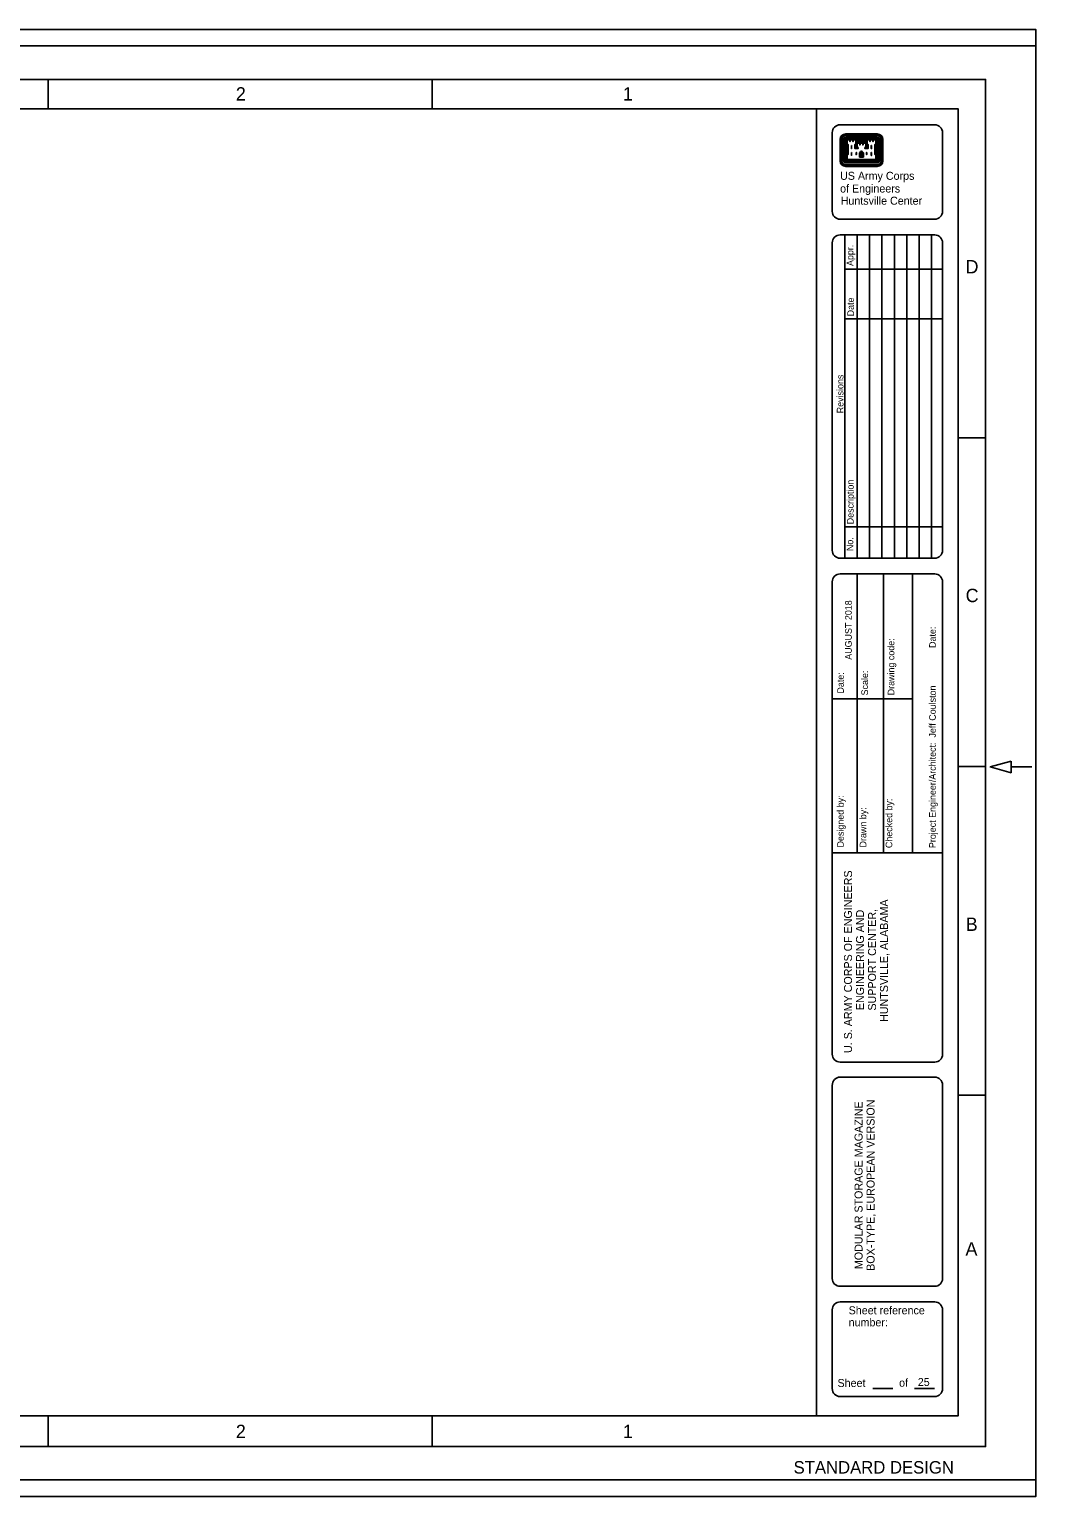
# Model space of a CAD drawing. Extents: x -0.04 to 2.79, y -0.02 to 1.81.
# Drawn here: x 1.534 to 2.792, y -0.021 to 1.813 of the extents above; entities that cross this region are included whole.
import ezdxf

# ---------------------------------------------------------------- set-up
doc = ezdxf.new("R2010")
doc.units = 0
for name, color, linetype in [('G-ANNO-NPLT', 7, 'Continuous'), ('G-ANNO-PLOT', 7, 'Continuous'), ('G-ANNO-TTLB', 7, 'Continuous')]:
    doc.layers.add(name, color=color, linetype=linetype)

msp = doc.modelspace()

# ---------------------------------------------------------------- linework, layer by layer
at = {"layer": 'G-ANNO-NPLT'}
msp.add_lwpolyline([(-0.0417, 1.8125), (2.7917, 1.8125), (2.7917, -0.0208), (-0.0417, -0.0208)], close=True, dxfattribs=at)
at = {"layer": 'G-ANNO-PLOT'}
for p, q in [((2.7917, 1.8125), (-0.0417, 1.8125)), ((2.7917, 1.8125), (2.7917, -0.0208)), ((2.7917, -0.0208), (-0.0417, -0.0208))]:
    msp.add_line(p, q, dxfattribs=at)
msp.add_lwpolyline([(0, 0), (2.7917, 0), (2.7917, 1.7917), (0, 1.7917)], close=True, dxfattribs=at)
at = {"layer": 'G-ANNO-TTLB'}
for p, q in [((1.5578, 1.7131), (1.5578, 1.75)), ((2.0378, 1.7131), (2.0378, 1.75)), ((2.5178, 0.0803), (2.5178, 1.7131)), ((2.5473, 1.6749), (2.5473, 1.6483)), ((2.5477, 1.6749), (2.5477, 1.6483)), ((2.5484, 1.6749), (2.5484, 1.6483)), ((2.5489, 1.6749), (2.5489, 1.6483)), ((2.5494, 1.6749), (2.5494, 1.6483)), ((2.5517, 1.6749), (2.5517, 1.6483)), ((2.5523, 1.6749), (2.5523, 1.6483)), ((2.5528, 1.6749), (2.5528, 1.6483)), ((2.5534, 1.6749), (2.5534, 1.6483)), ((2.554, 1.6749), (2.554, 1.6483)), ((2.5938, 1.6819), (2.5543, 1.6819)), ((2.5938, 1.6815), (2.5543, 1.6815)), ((2.5938, 1.6809), (2.5543, 1.6809)), ((2.5938, 1.6804), (2.5543, 1.6804)), ((2.5938, 1.6798), (2.5543, 1.6798)), ((2.5938, 1.6776), (2.5543, 1.6776)), ((2.5938, 1.677), (2.5543, 1.677)), ((2.5938, 1.6764), (2.5543, 1.6764)), ((2.5938, 1.6758), (2.5543, 1.6758)), ((2.5938, 1.6753), (2.5543, 1.6753)), ((2.5545, 1.6749), (2.5545, 1.6484)), ((2.5551, 1.6749), (2.5551, 1.649)), ((2.5555, 1.6692), (2.5555, 1.6556)), ((2.5561, 1.6686), (2.5561, 1.6563)), ((2.5679, 1.6747), (2.5801, 1.6747)), ((2.5679, 1.6742), (2.5801, 1.6742)), ((2.5679, 1.6737), (2.5801, 1.6737)), ((2.5679, 1.6731), (2.5801, 1.6731)), ((2.5679, 1.6725), (2.5801, 1.6725)), ((2.5679, 1.672), (2.5801, 1.672)), ((2.5679, 1.6714), (2.5801, 1.6714)), ((2.592, 1.6686), (2.592, 1.6563)), ((2.5925, 1.6692), (2.5925, 1.6557)), ((2.593, 1.6749), (2.593, 1.649)), ((2.5935, 1.6749), (2.5935, 1.6484)), ((2.5941, 1.6749), (2.5941, 1.6483)), ((2.5947, 1.6749), (2.5947, 1.6483)), ((2.5953, 1.6749), (2.5953, 1.6483)), ((2.5958, 1.6749), (2.5958, 1.6483)), ((2.5964, 1.6749), (2.5964, 1.6483)), ((2.5986, 1.6749), (2.5986, 1.6483)), ((2.5992, 1.6749), (2.5992, 1.6483)), ((2.5997, 1.6749), (2.5997, 1.6483)), ((2.6003, 1.6749), (2.6003, 1.6483)), ((2.6007, 1.6749), (2.6007, 1.6483)), ((2.5714, 1.6528), (2.5714, 1.6572)), ((2.5714, 1.6528), (2.5767, 1.6528)), ((2.5719, 1.6528), (2.5719, 1.6572)), ((2.5725, 1.6528), (2.5725, 1.6572)), ((2.5731, 1.6528), (2.5731, 1.6572)), ((2.5737, 1.6528), (2.5737, 1.6572)), ((2.5744, 1.6528), (2.5744, 1.6572)), ((2.575, 1.6528), (2.575, 1.6572)), ((2.5755, 1.6528), (2.5755, 1.6572)), ((2.5761, 1.6528), (2.5761, 1.6572)), ((2.5767, 1.6528), (2.5767, 1.6572)), ((2.5938, 1.6478), (2.5543, 1.6478)), ((2.5938, 1.6473), (2.5543, 1.6473)), ((2.5938, 1.6467), (2.5543, 1.6467)), ((2.5938, 1.6462), (2.5543, 1.6462)), ((2.5938, 1.6456), (2.5543, 1.6456)), ((2.5938, 1.6433), (2.5543, 1.6433)), ((2.5938, 1.6428), (2.5543, 1.6428)), ((2.5938, 1.6423), (2.5543, 1.6423)), ((2.5938, 1.6417), (2.5543, 1.6417)), ((2.5938, 1.6412), (2.5543, 1.6412)), ((2.5935, 1.6484), (2.5545, 1.6484)), ((2.593, 1.649), (2.5551, 1.649)), ((2.5532, 1.5557), (2.5532, 1.1517)), ((2.5686, 1.5557), (2.5686, 1.1517)), ((2.5842, 1.5557), (2.5842, 1.1517)), ((2.5996, 1.5557), (2.5996, 1.1517)), ((2.6151, 1.5557), (2.6151, 1.1517)), ((2.6306, 1.5557), (2.6306, 1.1517)), ((2.646, 1.5557), (2.646, 1.1517)), ((2.6615, 1.5557), (2.6615, 1.1517)), ((2.5532, 1.513), (2.6754, 1.513)), ((2.5532, 1.4507), (2.6754, 1.4507)), ((2.695, 1.3022), (2.7292, 1.3022)), ((2.5532, 1.1911), (2.6754, 1.1911)), ((2.5685, 1.1321), (2.5685, 0.976)), ((2.6014, 1.1321), (2.6014, 0.976)), ((2.6377, 1.1321), (2.6377, 0.7837)), ((2.6377, 0.976), (2.5376, 0.976)), ((2.5685, 0.976), (2.5685, 0.7837)), ((2.6014, 0.976), (2.6014, 0.7837)), ((2.695, 0.8914), (2.7292, 0.8914)), ((2.7609, 0.891), (2.787, 0.891)), ((2.6754, 0.7837), (2.5376, 0.7837)), ((2.5474, 0.5221), (2.6655, 0.5221)), ((2.695, 0.4806), (2.7292, 0.4806)), ((2.5883, 0.1141), (2.6134, 0.1141)), ((2.6403, 0.1141), (2.6654, 0.1141)), ((1.5578, 0.0418), (1.5578, 0.0803)), ((2.0378, 0.0418), (2.0378, 0.0803))]:
    msp.add_line(p, q, dxfattribs=at)
for points in [[(0.0833, 0.0417), (2.7292, 0.0417), (2.7292, 1.75), (0.2515, 1.75)], [(0.1166, 0.0803), (2.695, 0.0803), (2.695, 1.7131), (0.1166, 1.7131)], [(2.5474, 1.6934), (2.6655, 1.6934)], [(2.5376, 1.5851), (2.5376, 1.6835)], [(2.5555, 1.6749), (2.5555, 1.6698), (2.5567, 1.6686), (2.5567, 1.6563), (2.5555, 1.6551), (2.5555, 1.6494), (2.5926, 1.6494), (2.5926, 1.6551), (2.5914, 1.6563), (2.5914, 1.6686), (2.5926, 1.6698), (2.5926, 1.6749), (2.5877, 1.6749), (2.5839, 1.6749), (2.5804, 1.6749), (2.5804, 1.6698), (2.5817, 1.6686), (2.5817, 1.6642), (2.5789, 1.6642), (2.5789, 1.6646), (2.5801, 1.6657), (2.5801, 1.6708), (2.5752, 1.6708), (2.5714, 1.6708), (2.5679, 1.6708), (2.5679, 1.6657), (2.5691, 1.6646), (2.5691, 1.6642), (2.5664, 1.6642), (2.5664, 1.6686), (2.5676, 1.6698), (2.5676, 1.6749), (2.5626, 1.6749), (2.5589, 1.6749), (2.5555, 1.6749)], [(2.5561, 1.6743), (2.5561, 1.67), (2.5573, 1.6688), (2.5573, 1.656), (2.5561, 1.6549), (2.5561, 1.65), (2.592, 1.65), (2.592, 1.6549), (2.5909, 1.656), (2.5909, 1.6688), (2.592, 1.67), (2.592, 1.6743), (2.5886, 1.6743), (2.5886, 1.6723), (2.5883, 1.6723), (2.5883, 1.6743), (2.5848, 1.6743), (2.5848, 1.6723), (2.5845, 1.6723), (2.5845, 1.6743), (2.581, 1.6743), (2.581, 1.67), (2.5822, 1.6688), (2.5822, 1.6636), (2.5784, 1.6636), (2.5784, 1.6648), (2.5796, 1.6659), (2.5796, 1.6703), (2.5761, 1.6703), (2.5761, 1.6682), (2.5757, 1.6682), (2.5757, 1.6703), (2.5723, 1.6703), (2.5723, 1.6682), (2.5719, 1.6682), (2.5719, 1.6703), (2.5685, 1.6703), (2.5685, 1.6659), (2.5697, 1.6648), (2.5697, 1.6636), (2.5658, 1.6636), (2.5658, 1.6688), (2.5671, 1.67), (2.5671, 1.6743), (2.5636, 1.6743), (2.5636, 1.6723), (2.5633, 1.6723), (2.5633, 1.6743), (2.5598, 1.6743), (2.5598, 1.6723), (2.5595, 1.6723), (2.5595, 1.6743), (2.5561, 1.6743)], [(2.5673, 1.6687), (2.567, 1.6684), (2.567, 1.6647), (2.5682, 1.6647), (2.5674, 1.6655), (2.5674, 1.6688)], [(2.5807, 1.6687), (2.581, 1.6684), (2.581, 1.6647), (2.5799, 1.6647), (2.5807, 1.6655), (2.5807, 1.6688)], [(2.6754, 1.6835), (2.6754, 1.5851)], [(2.5614, 1.6674), (2.5614, 1.6636), (2.5617, 1.6636), (2.5617, 1.6674), (2.5614, 1.6674)], [(2.5614, 1.6587), (2.5614, 1.6549), (2.5617, 1.6549), (2.5617, 1.6587), (2.5614, 1.6587)], [(2.5673, 1.6587), (2.5673, 1.6561), (2.5677, 1.6561), (2.5677, 1.6587), (2.5673, 1.6587)], [(2.5807, 1.6587), (2.5807, 1.6561), (2.5804, 1.6561), (2.5804, 1.6587), (2.5807, 1.6587)], [(2.5867, 1.6674), (2.5867, 1.6636), (2.5863, 1.6636), (2.5863, 1.6674), (2.5867, 1.6674)], [(2.5867, 1.6587), (2.5867, 1.6549), (2.5863, 1.6549), (2.5863, 1.6587), (2.5867, 1.6587)], [(2.6655, 1.5753), (2.5474, 1.5753)], [(2.5376, 1.5458), (2.5376, 1.1615)], [(2.6655, 1.5557), (2.5474, 1.5557)], [(2.6754, 1.1615), (2.6754, 1.5458)], [(2.5474, 1.1517), (2.6655, 1.1517)], [(2.5376, 1.1223), (2.5376, 0.5321)], [(2.6655, 1.1321), (2.5474, 1.1321)], [(2.6754, 0.5319), (2.6754, 1.1223)], [(2.6655, 0.5033), (2.5474, 0.5033)], [(2.5376, 0.493), (2.5376, 0.2518)], [(2.6754, 0.2518), (2.6754, 0.4935)], [(2.5474, 0.242), (2.6655, 0.242)], [(2.5474, 0.2224), (2.6655, 0.2224)], [(2.5376, 0.1141), (2.5376, 0.2126)], [(2.6754, 0.2126), (2.6754, 0.1141)], [(2.6655, 0.1043), (2.5474, 0.1043)]]:
    msp.add_lwpolyline(points, dxfattribs=at)
msp.add_lwpolyline([(2.7609, 0.8983), (2.735, 0.891), (2.7609, 0.8837)], close=True, dxfattribs=at)
for centre, major_axis, start_param, end_param in [((2.5474, 1.6835), (-0.00984, 0), 4.712389, 6.283185), ((2.6655, 1.6835), (-0.00984, 0), 3.141593, 4.712389), ((2.5543, 1.6749), (-0.00696, 0), 4.712389, 6.283185), ((2.5543, 1.6749), (-0.00656, 0), 4.712389, 6.283185), ((2.5543, 1.6749), (-0.006, 0), 4.712389, 6.283185), ((2.5543, 1.6749), (-0.00543, 0), 4.712389, 6.283185), ((2.5543, 1.6749), (-0.00487, 0), 4.712389, 6.283185), ((2.5543, 1.6749), (-0.00261, 0), 4.712389, 6.283185), ((2.5543, 1.6749), (-0.00205, 0), 4.712389, 6.283185), ((2.5543, 1.6749), (-0.00148, 0), 4.712389, 6.283185), ((2.5543, 1.6749), (0.000919, 0), 1.570796, 3.141593), ((2.5543, 1.6749), (-0.000355, 0), 4.712389, 6.283185), ((2.5938, 1.6749), (-0.00696, 0), 3.141593, 4.712389), ((2.5938, 1.6749), (0.00656, 0), 0, 1.570796), ((2.5938, 1.6749), (0.006, 0), 0, 1.570796), ((2.5938, 1.6749), (0.00543, 0), 0, 1.570796), ((2.5938, 1.6749), (0.00487, 0), 0, 1.570796), ((2.5938, 1.6749), (-0.00261, 0), 3.141593, 4.712389), ((2.5938, 1.6749), (-0.00205, 0), 3.141593, 4.712389), ((2.5938, 1.6749), (-0.00148, 0), 3.141593, 4.712389), ((2.5938, 1.6749), (-0.000919, 0), 3.141593, 4.712389), ((2.5938, 1.6749), (-0.000355, 0), 3.141593, 4.712389), ((2.575, 1.6569), (0.00361, 0), 1.844255, 3.072783), ((2.575, 1.6569), (-0.00304, 0), 4.947481, 6.214375), ((2.575, 1.6569), (-0.00248, 0), 4.947481, 6.214375), ((2.575, 1.6569), (-0.00192, 0), 4.947481, 6.214375), ((2.5731, 1.6569), (0.00135, 0), 0.06881, 1.335704), ((2.5731, 1.6569), (0.00192, 0), 0.06881, 1.335704), ((2.5731, 1.6569), (-0.00248, 0), 3.210403, 4.477297), ((2.575, 1.6569), (-0.00135, 0), 4.947481, 6.214375), ((2.5731, 1.6569), (0.00304, 0), 0.06881, 1.335704), ((2.5731, 1.6569), (0.00361, 0), 0.06881, 1.298435), ((2.5543, 1.6482), (0.00696, 0), 3.141593, 4.712389), ((2.5543, 1.6482), (0.00656, 0), 3.141593, 4.712389), ((2.5543, 1.6482), (-0.006, 0), 0, 1.570796), ((2.5543, 1.6482), (0.00543, 0), 3.141593, 4.712389), ((2.5543, 1.6482), (0.00487, 0), 3.141593, 4.712389), ((2.5543, 1.6482), (0.00261, 0), 3.141593, 4.712389), ((2.5543, 1.6482), (0.00205, 0), 3.141593, 4.712389), ((2.5543, 1.6482), (0.00148, 0), 3.141593, 4.712389), ((2.5543, 1.6482), (0.000919, 0), 3.141593, 4.712389), ((2.5543, 1.6482), (0.000355, 0), 3.141593, 4.712389), ((2.5938, 1.6482), (0.00696, 0), 4.712389, 6.283185), ((2.5938, 1.6482), (0.00261, 0), 4.712389, 6.283185), ((2.5938, 1.6482), (0.00205, 0), 4.712389, 6.283185), ((2.5938, 1.6482), (0.00148, 0), 4.712389, 6.283185), ((2.5938, 1.6482), (0.000919, 0), 4.712389, 6.283185), ((2.5938, 1.6482), (0.000355, 0), 4.712389, 6.283185), ((2.5938, 1.6482), (0.00487, 0), 4.712389, 6.283185), ((2.5938, 1.6482), (0.00543, 0), 4.712389, 6.283185), ((2.5938, 1.6482), (0.006, 0), 4.712389, 6.283185), ((2.5938, 1.6482), (0.00656, 0), 4.712389, 6.283185), ((2.5474, 1.5851), (-0.00984, 0), 0, 1.570796), ((2.6655, 1.5851), (0.00984, 0), 4.712389, 6.283185), ((2.5474, 1.5458), (-0.00984, 0), 4.712389, 6.281588), ((2.6655, 1.5458), (-0.00984, 0), 3.141593, 4.712389), ((2.5474, 1.1615), (-0.00984, 0), 0, 1.570796), ((2.6655, 1.1615), (0.00984, 0), 4.712389, 6.283185), ((2.5474, 1.1223), (-0.00984, 0), 4.712389, 6.283185), ((2.6655, 1.1223), (-0.00984, 0), 3.141593, 4.712389), ((2.5474, 0.5319), (-0.00984, 0), 6.267222, 7.853982), ((2.6655, 0.5319), (0.00984, 0), 4.712389, 6.283185), ((2.5474, 0.4935), (-0.00984, 0), 4.712389, 6.327939), ((2.6655, 0.4935), (0.00984, 0), 0, 1.570796), ((2.5474, 0.2518), (-0.00984, 0), 0, 1.570796), ((2.6655, 0.2518), (0.00984, 0), 4.712389, 6.283185), ((2.5474, 0.2126), (-0.00984, 0), 4.712389, 6.283185), ((2.6655, 0.2126), (0.00984, 0), 0, 1.570796), ((2.5474, 0.1141), (-0.00984, 0), 0, 1.570796), ((2.6655, 0.1141), (0.00984, 0), 4.712389, 6.283185)]:
    msp.add_ellipse(centre, major_axis=major_axis, ratio=0.999936, start_param=start_param, end_param=end_param, dxfattribs=at)

# ---------------------------------------------------------------- texts
for s, height, p in [('2', 0.0167, (1.7923, 1.7235)), ('1', 0.0167, (2.2759, 1.7235)), ('US Army Corps', 0.01, (2.5473, 1.6245)), ('of Engineers', 0.01, (2.5473, 1.6086)), ('Huntsville Center', 0.01, (2.548, 1.5934)), ('D', 0.0167, (2.7041, 1.5076)), ('D', 0.0167, (2.7041, 1.5076)), ('C', 0.0167, (2.7042, 1.0968)), ('B', 0.0167, (2.7043, 0.686)), ('A', 0.0167, (2.704, 0.2804)), ('Sheet reference', 0.01, (2.558, 0.207)), ('number:', 0.01, (2.558, 0.192)), ('Sheet', 0.01, (2.5441, 0.1162)), ('of', 0.01, (2.621, 0.1165)), ('25', 0.01, (2.6444, 0.1174)), ('2', 0.0167, (1.7923, 0.0523)), ('1', 0.0167, (2.2759, 0.0523)), ('STANDARD DESIGN', 0.015583, (2.4892, 0.008))]:
    msp.add_text(s, height=height, dxfattribs=at).set_placement(p)
for s, height, p in [('Appr.', 0.00833, (2.5639, 1.5168)), ('Date', 0.00833, (2.5646, 1.4539)), ('Revisions', 0.00833, (2.5515, 1.3328)), ('Description', 0.008333, (2.5642, 1.1941)), ('No.', 0.00833, (2.5637, 1.1606)), ('AUGUST 2018', 0.008333, (2.5619, 1.0248)), ('Date:', 0.00833, (2.6669, 1.0396)), ('Drawing code:', 0.008333, (2.6151, 0.9804)), ('Scale:', 0.00833, (2.5822, 0.9803)), ('Date:', 0.00833, (2.552, 0.9826)), ('Project Engineer/Architect:  Jeff Coulston', 0.008333, (2.6669, 0.7895)), ('Designed by:', 0.008333, (2.5519, 0.7903)), ('Checked by:', 0.008333, (2.6125, 0.7895)), ('Drawn by:', 0.00833, (2.5801, 0.7903)), ('U. S. ARMY CORPS OF ENGINEERS', 0.01, (2.5622, 0.5335)), ('HUNTSVILLE, ALABAMA', 0.01, (2.6072, 0.5723)), ('ENGINEERING AND', 0.01, (2.5772, 0.587)), ('SUPPORT CENTER,', 0.01, (2.5922, 0.5865)), ('MODULAR STORAGE MAGAZINE', 0.01, (2.5754, 0.2635)), ('BOX-TYPE, EUROPEAN VERSION', 0.01, (2.5904, 0.2613))]:
    msp.add_text(s, height=height, rotation=90, dxfattribs=at).set_placement(p)

doc.saveas('drawing.dxf')
